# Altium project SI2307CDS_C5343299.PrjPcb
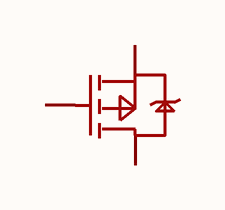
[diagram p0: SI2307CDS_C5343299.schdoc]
1 sheet, 1 parts. Net scope: global (net labels, ports and power ports of the same name join across sheets).

## Sheet SI2307CDS_C5343299.schdoc
size 127 x 101 mm

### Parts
Q?  si2307cds_c5343299  [SOT-23-3_L2.9-W1.3-P1.90-LS2.4-BR]  (value not drawn)

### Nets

Not connected (* = marked no-connect by the designer): Q? 1(G) 2(S) 3(D)

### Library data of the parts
Q? = si2307cds_c5343299: 数量:1个P沟道;漏源电压(Vdss):30V;连续漏极电流(Id):3.4A;导通电阻(RDS(on)):75mΩ@10V;耗散功率(Pd):1.56W;阈值电压(Vgs(th)):1.6V;; Manufacturer: MSKSEMI(美森科); AddInBom: yes; ModelId: c62791f0466c4ae2a892c056b845b0ca; ModelName: SOT-23-3P_L2.9-W1.3-H1.0-LS2.4-P0.95; ModelTransform: 98.425,114.173,0,180,0,0,0.0005,-0.0005,0; Number: 1个P沟道; Drain to Source Voltage: 30V; Current - Continuous Drain(Id): 3.4A; Pd - Power Dissipation: 1.56W; Gate Threshold Voltage (Vgs(th)): 1.6V; Gate Charge(Qg): 2.5nC@4.5V; Input Capacitance(Ciss): 226pF; Reverse Transfer Capacitance (Crss@Vds): 29pF; Type: P沟道; Output Capacitance(Coss): 39pF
